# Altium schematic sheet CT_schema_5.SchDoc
size 469 x 363 mm
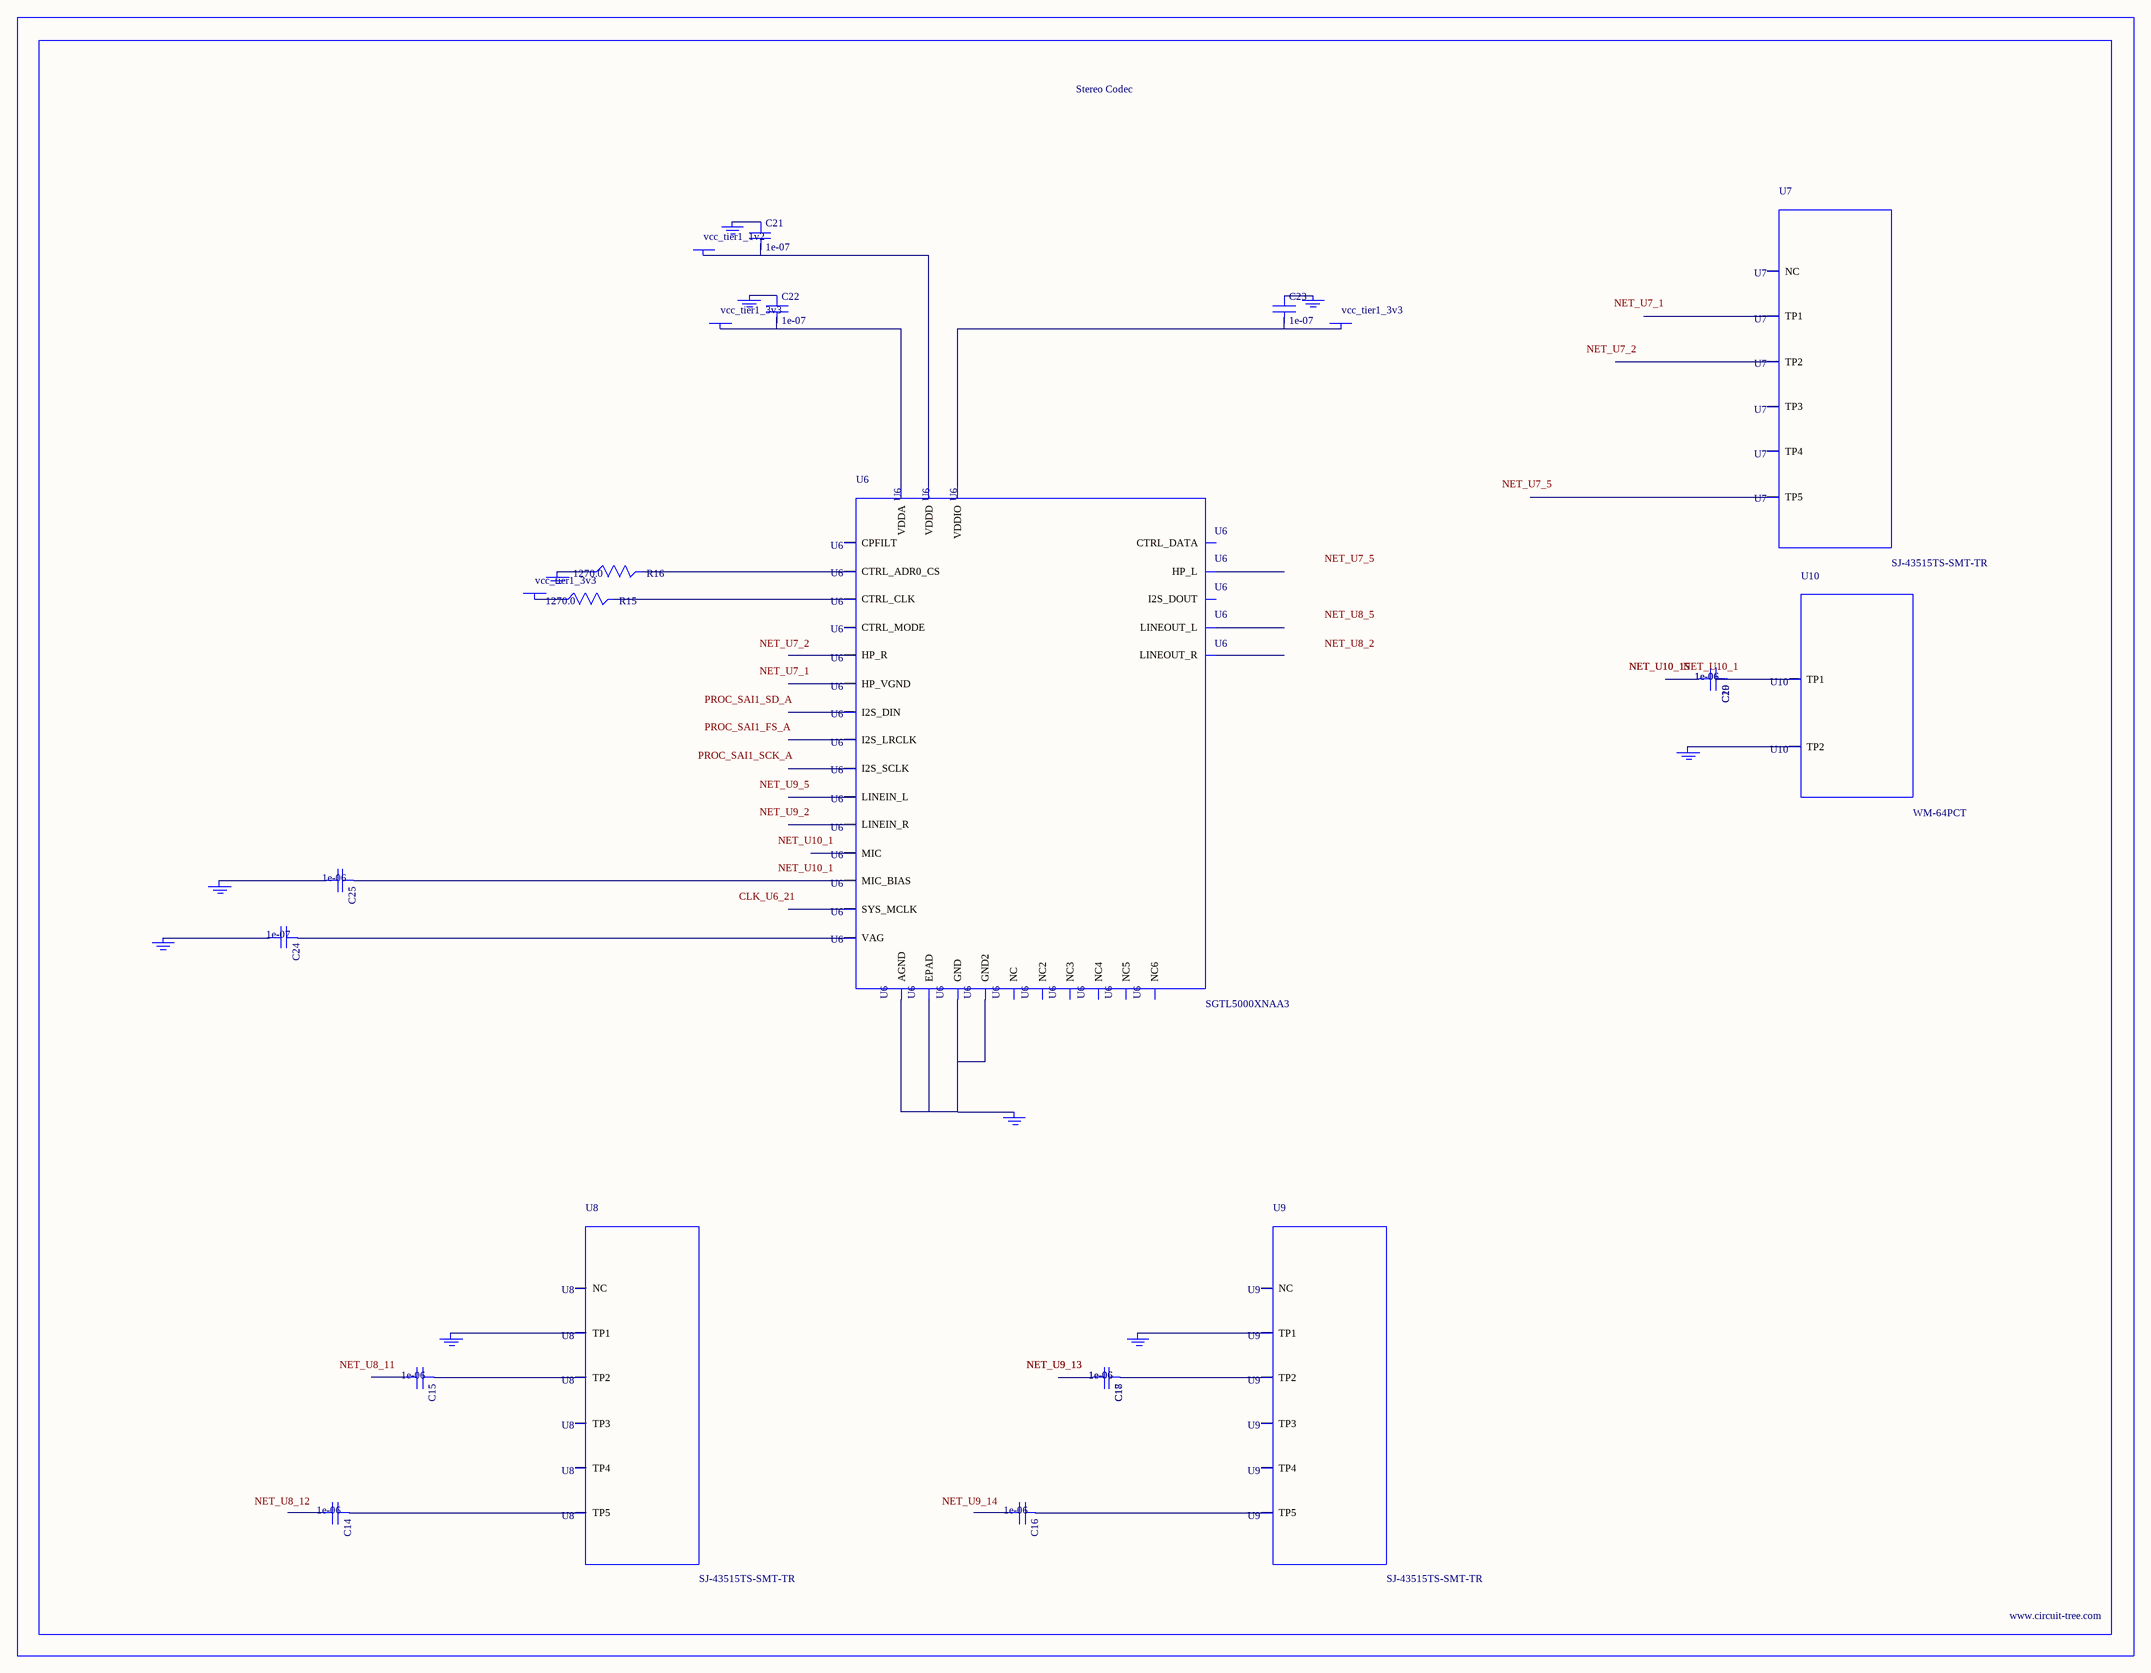
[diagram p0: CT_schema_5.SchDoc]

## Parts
BORDER4  (no value)
C14  1e-06  [C0603]
C15  1e-06  [C0603]
C16  1e-06  [C0603]
C17  1e-06  [C0603]
C18  1e-06  [C0603]
C19  1e-06  [C0603]
C20  1e-06  [C0603]
C21  1e-07  [C0402]
C22  1e-07  [C0402]
C23  1e-07  [C0402]
C24  1e-07  [C0402]
C25  1e-06  [C0603]
GND_INSTANCE_4_0  (no value)
GND_INSTANCE_4_1  (no value)
GND_INSTANCE_4_2  (no value)
GND_INSTANCE_4_3  (no value)
GND_INSTANCE_4_4  (no value)
GND_INSTANCE_4_5  (no value)
GND_INSTANCE_4_6  (no value)
GND_INSTANCE_4_7  (no value)
GND_INSTANCE_4_8  (no value)
GND_INSTANCE_4_9  (no value)
GND_INSTANCE_4_10  (no value)
POWER_INSTANCE_4_0  vcc_tier1_3v3
POWER_INSTANCE_4_1  vcc_tier1_3v3
POWER_INSTANCE_4_2  vcc_tier1_3v3
POWER_INSTANCE_4_3  vcc_tier1_1v2
R15  1270.0  [R0603]
R16  1270.0  [R0603]
U6  SGTL5000XNAA3  [QFN-32]
U7  SJ-43515TS-SMT-TR  [SJ-43515TS-SMT-TR]
U8  SJ-43515TS-SMT-TR  [SJ-43515TS-SMT-TR]
U9  SJ-43515TS-SMT-TR  [SJ-43515TS-SMT-TR]
U10  WM-64PCT  [WM-64PC]

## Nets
NetC14_1: C14.1 U8.5(TP5)
NetC15_1: C15.1 U8.2(TP2)
NetC16_1: C16.1 U9.5(TP5)
NetC17_1: C17.1 C18.1 U9.2(TP2)
NetC17_2: C17.2 C18.2
NetC19_1: C19.1 C20.1 U10.1(TP1)
NetC19_2: C19.2 C20.2
NetC21_1: C21.1 GND_INSTANCE_4_5.0(GND)
NetC21_2: C21.2 POWER_INSTANCE_4_3.0(PWR) U6.30(VDDD)
NetC22_1: C22.1 GND_INSTANCE_4_1.0(GND)
NetC22_2: C22.2 POWER_INSTANCE_4_0.0(PWR) U6.5(VDDA)
NetC23_1: C23.1 GND_INSTANCE_4_4.0(GND)
NetC23_2: C23.2 POWER_INSTANCE_4_1.0(PWR) U6.20(VDDIO)
NetC24_1: C24.1 U6.10(VAG)
NetC24_2: C24.2 GND_INSTANCE_4_2.0(GND)
NetC25_1: C25.1 U6.16(MIC_BIAS)
NetC25_2: C25.2 GND_INSTANCE_4_3.0(GND)
NetGND_INSTANCE_4_0_0: GND_INSTANCE_4_0.0(GND) U6.1(GND) U6.3(GND2) U6.7(AGND) U6.EXP(EPAD)
NetGND_INSTANCE_4_6_0: GND_INSTANCE_4_6.0(GND) R16.1
NetGND_INSTANCE_4_7_0: GND_INSTANCE_4_7.0(GND) U8.1(TP1)
NetGND_INSTANCE_4_8_0: GND_INSTANCE_4_8.0(GND) GND_INSTANCE_4_9.0(GND) U9.1(TP1)
NetGND_INSTANCE_4_10_0: GND_INSTANCE_4_10.0(GND) U10.2(TP2)
NetPOWER_INSTANCE_4_2_0: POWER_INSTANCE_4_2.0(PWR) R15.1
NetR15_2: R15.2 U6.29(CTRL_CLK)
NetR16_2: R16.2 U6.31(CTRL_ADR0_CS)

Not connected (* = marked no-connect by the designer): C14 2; C15 2; C16 2; U6 2(HP_R) 4(HP_VGND) 6(HP_L) 8(NC) 9(NC2) 11(LINEOUT_R) 12(LINEOUT_L) 13(LINEIN_R) 14(LINEIN_L) 15(MIC) 17(NC3) 18(CPFILT) 19(NC4) 21(SYS_MCLK) 22(NC5) 23(I2S_LRCLK) 24(I2S_SCLK) 25(I2S_DOUT) 26(I2S_DIN) 27(CTRL_DATA) 28(NC6) 32(CTRL_MODE); U7 1(TP1) 2(TP2) 3(TP3) 4(TP4) 5(TP5) 6(NC); U8 3(TP3) 4(TP4) 6(NC); U9 3(TP3) 4(TP4) 6(NC)

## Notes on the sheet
- Labels drawn without touching a wire or pin: CLK_U6_21, NET_U7_1, NET_U7_2, NET_U7_5, NET_U8_2, NET_U8_5, NET_U8_11, NET_U8_12, NET_U9_2, NET_U9_5, NET_U9_14, NET_U10_1, PROC_SAI1_FS_A, PROC_SAI1_SCK_A, PROC_SAI1_SD_A

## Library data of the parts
BORDER4 = BORDER_PAGE4
C14-C20 C25 = C0603C105K3RACTU
C21-C24 = C0402C104K3RACTU
GND_INSTANCE_4_0-GND_INSTANCE_4_10 = GND
POWER_INSTANCE_4_0-POWER_INSTANCE_4_3 = PWR
R15 R16 = RC0603FR-071K27L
